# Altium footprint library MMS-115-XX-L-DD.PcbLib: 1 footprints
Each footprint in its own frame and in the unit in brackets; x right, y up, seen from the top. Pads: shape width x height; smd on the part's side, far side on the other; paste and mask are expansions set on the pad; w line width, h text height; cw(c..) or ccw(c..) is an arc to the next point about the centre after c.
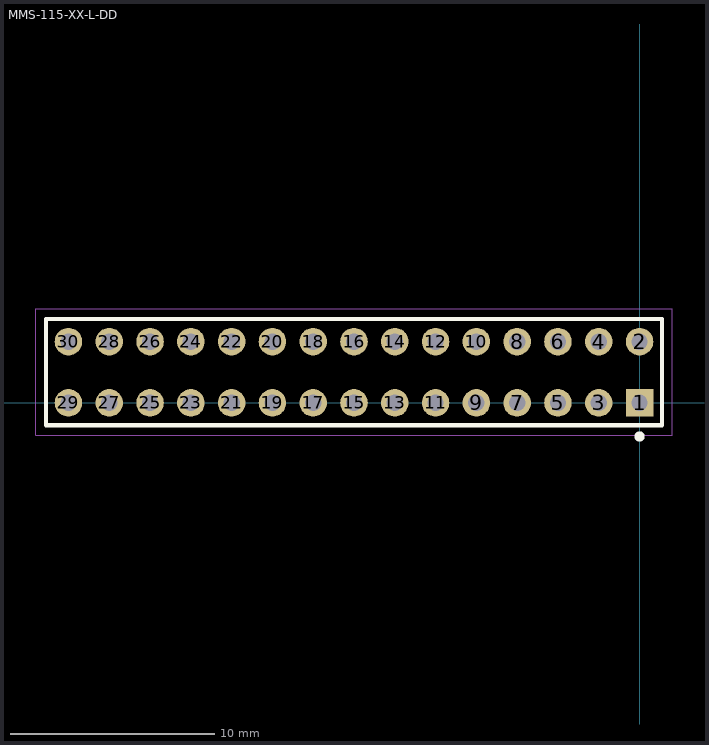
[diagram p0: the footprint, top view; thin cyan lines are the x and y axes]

## MMS-115-XX-L-DD [mm] "2.00mm pitch, 30 pin, socket strip; vertical, double row, PTH"
height 4.44
pads (30):
  rect 1.35x1.35 / inner round 1.35 / far side rect 1.35x1.35 hole 0.8 mask+0: 1(0,0)
  round 1.35 hole 0.8 mask+0: 2(0,3) 3(-2,0) 4(-2,3) 5(-4,0) 6(-4,3) 7(-6,0) 8(-6,3) 9(-8,0) 10(-8,3) 11(-10,0) 12(-10,3) 13(-12,0) 14(-12,3) 15(-14,0) 16(-14,3) 17(-16,0) 18(-16,3) 19(-18,0) 20(-18,3) 21(-20,0) 22(-20,3) 23(-22,0) 24(-22,3) 25(-24,0) 26(-24,3) 27(-26,0) 28(-26,3) 29(-28,0) 30(-28,3)
Top Overlay:
  circle w0.25: c0,-1.65 r0.125
  lines w0.2: -29.1,-1.1 1.1,-1.1 1.1,4.1 -29.1,4.1 -29.1,-1.1
Mechanical 12:
  lines w0.001: -29.1,-1.1 1.1,-1.1 1.1,4.1 -29.1,4.1 -29.1,-1.1
Mechanical 13:
  circle w0.1: c0,-1.65 r0.125
  lines w0.1: -29.1,-1.1 1.1,-1.1 1.1,4.1 -29.1,4.1 -29.1,-1.1
  text ".Designator" at 0.254,0.254 h1.52
Mechanical 15:
  lines w0.05: -29.6,-1.6 1.6,-1.6 1.6,4.6 -29.6,4.6 -29.6,-1.6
